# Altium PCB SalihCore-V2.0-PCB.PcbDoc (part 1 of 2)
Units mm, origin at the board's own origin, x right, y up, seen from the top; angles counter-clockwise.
Board outline 97.26 x 87.25 mm, 4 copper layers (L1(sig), L2(GND), L3(PWR), L4(sig)), stack 1.589 mm thick; 79 components, 110 nets, 368 pads, 235 vias.
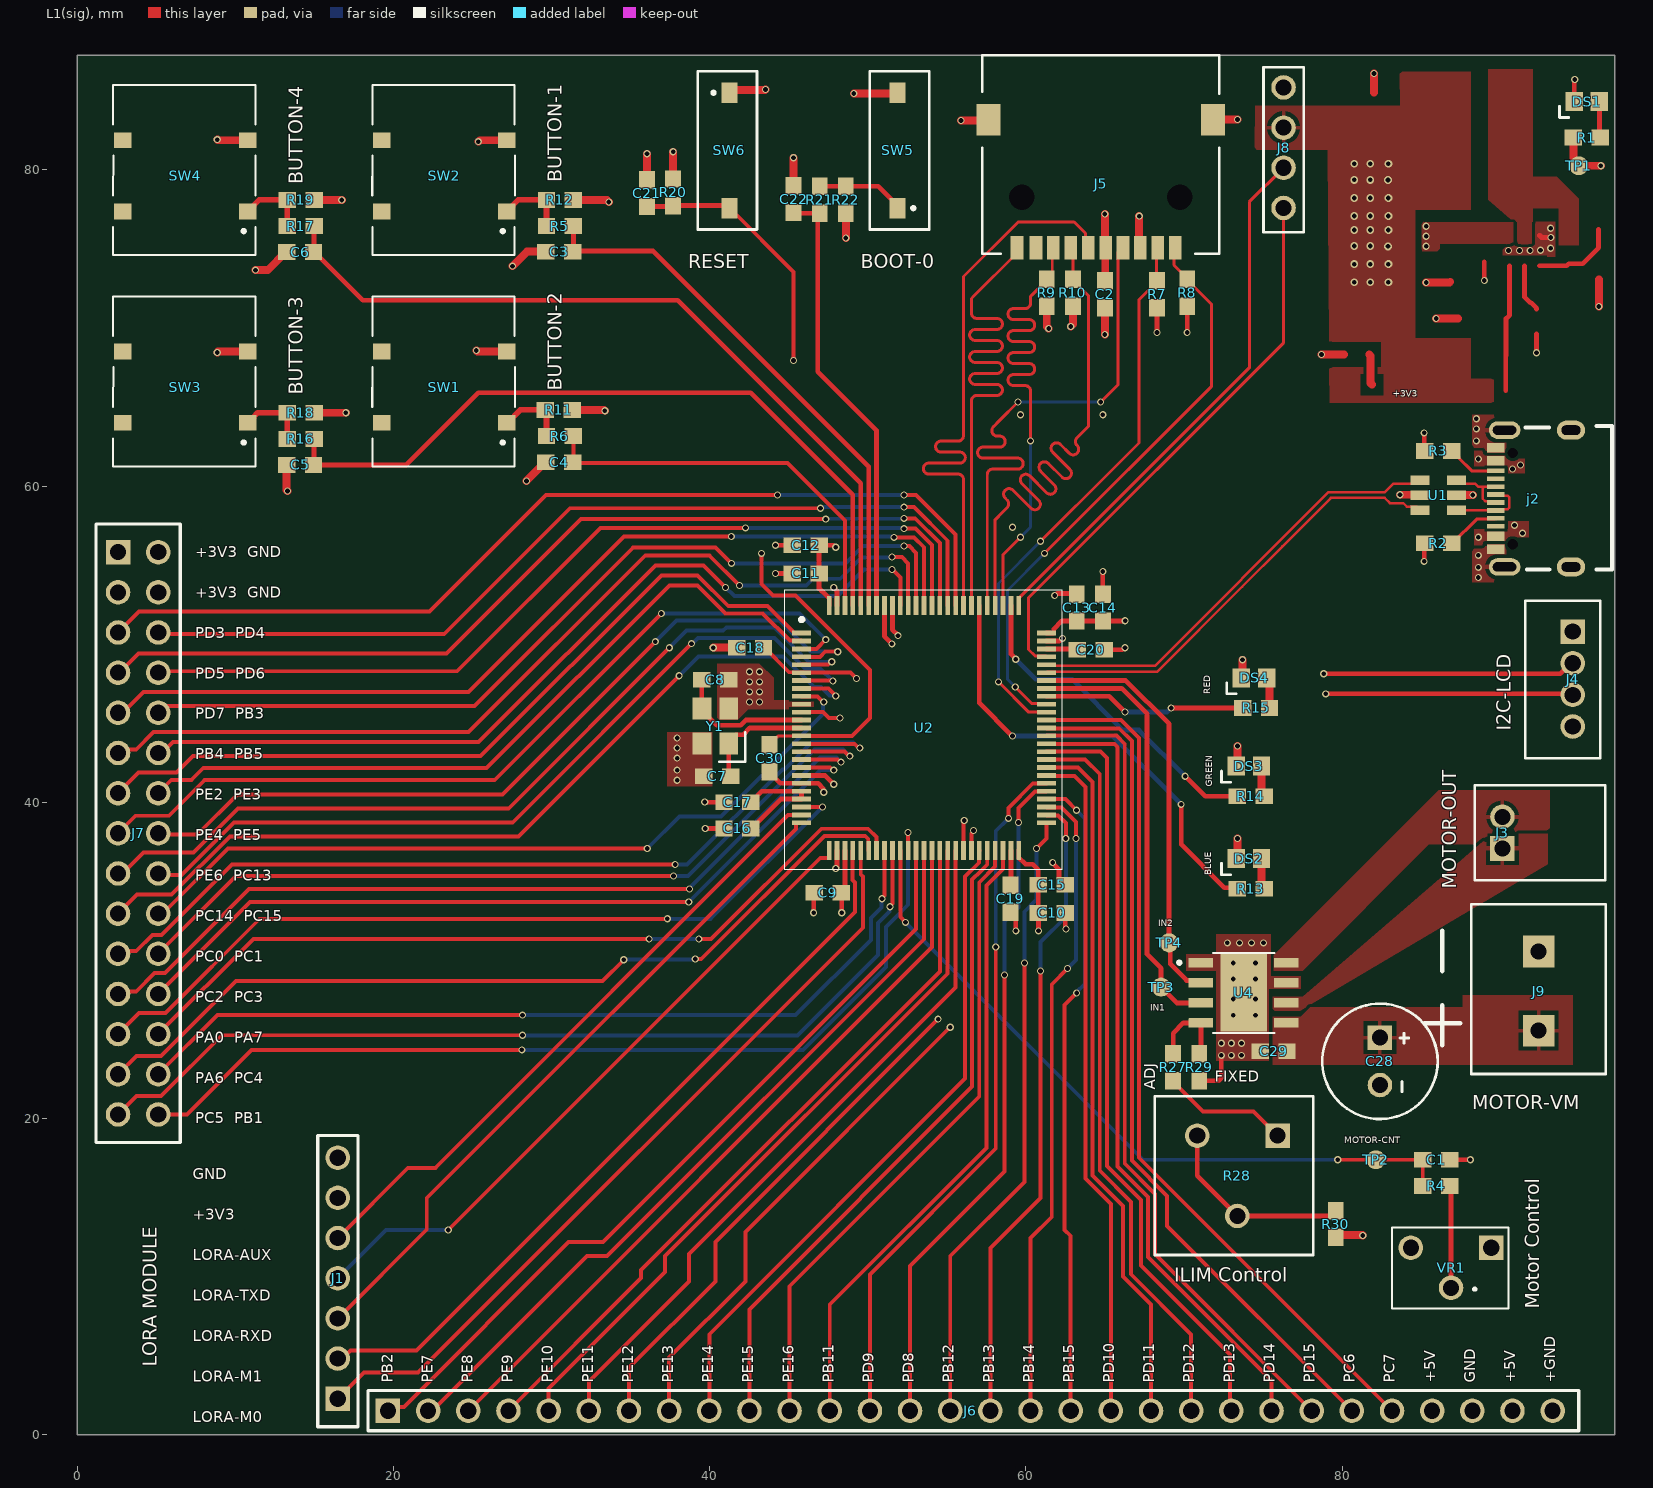
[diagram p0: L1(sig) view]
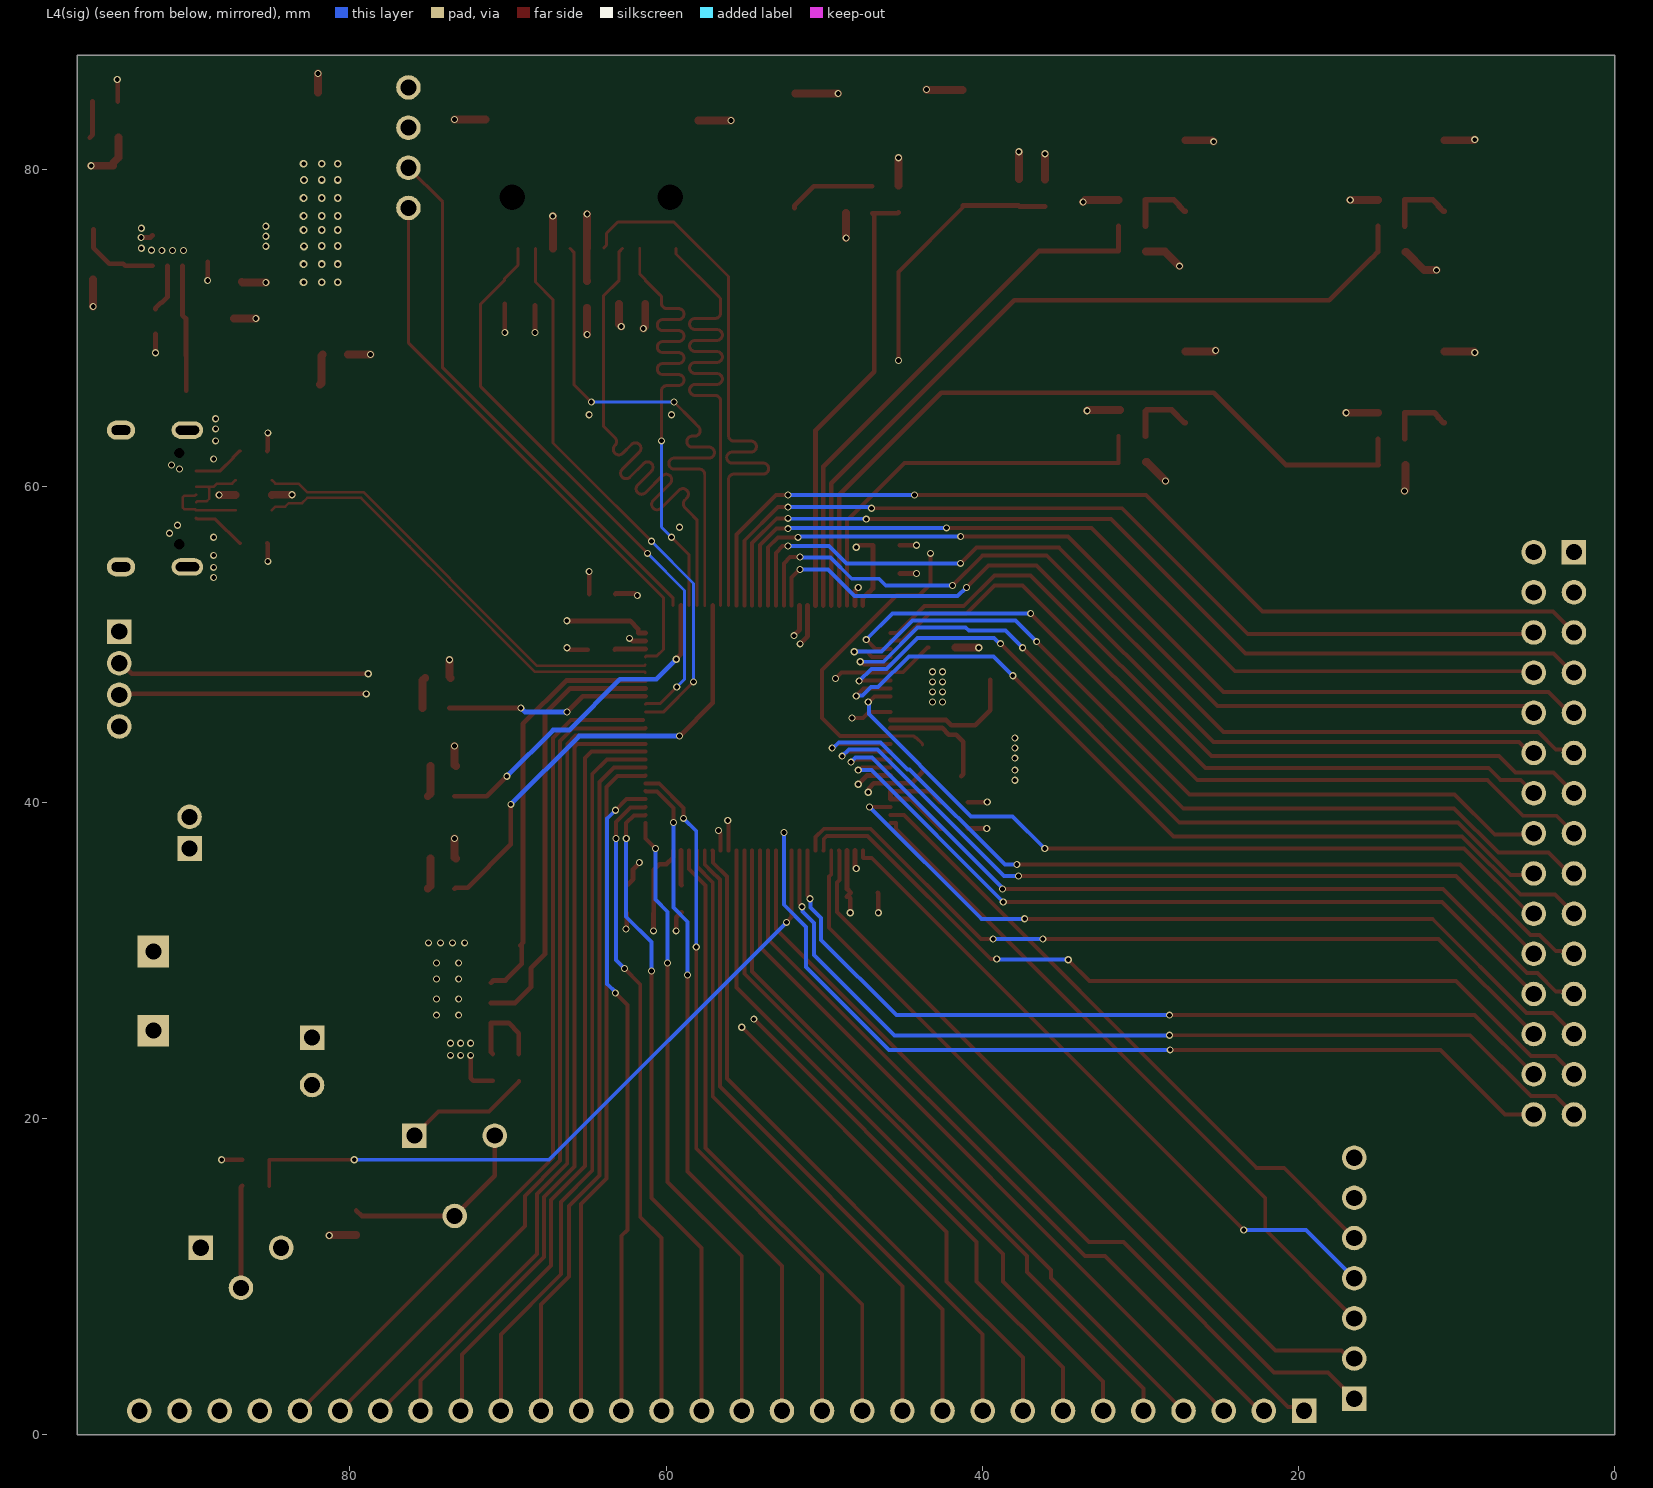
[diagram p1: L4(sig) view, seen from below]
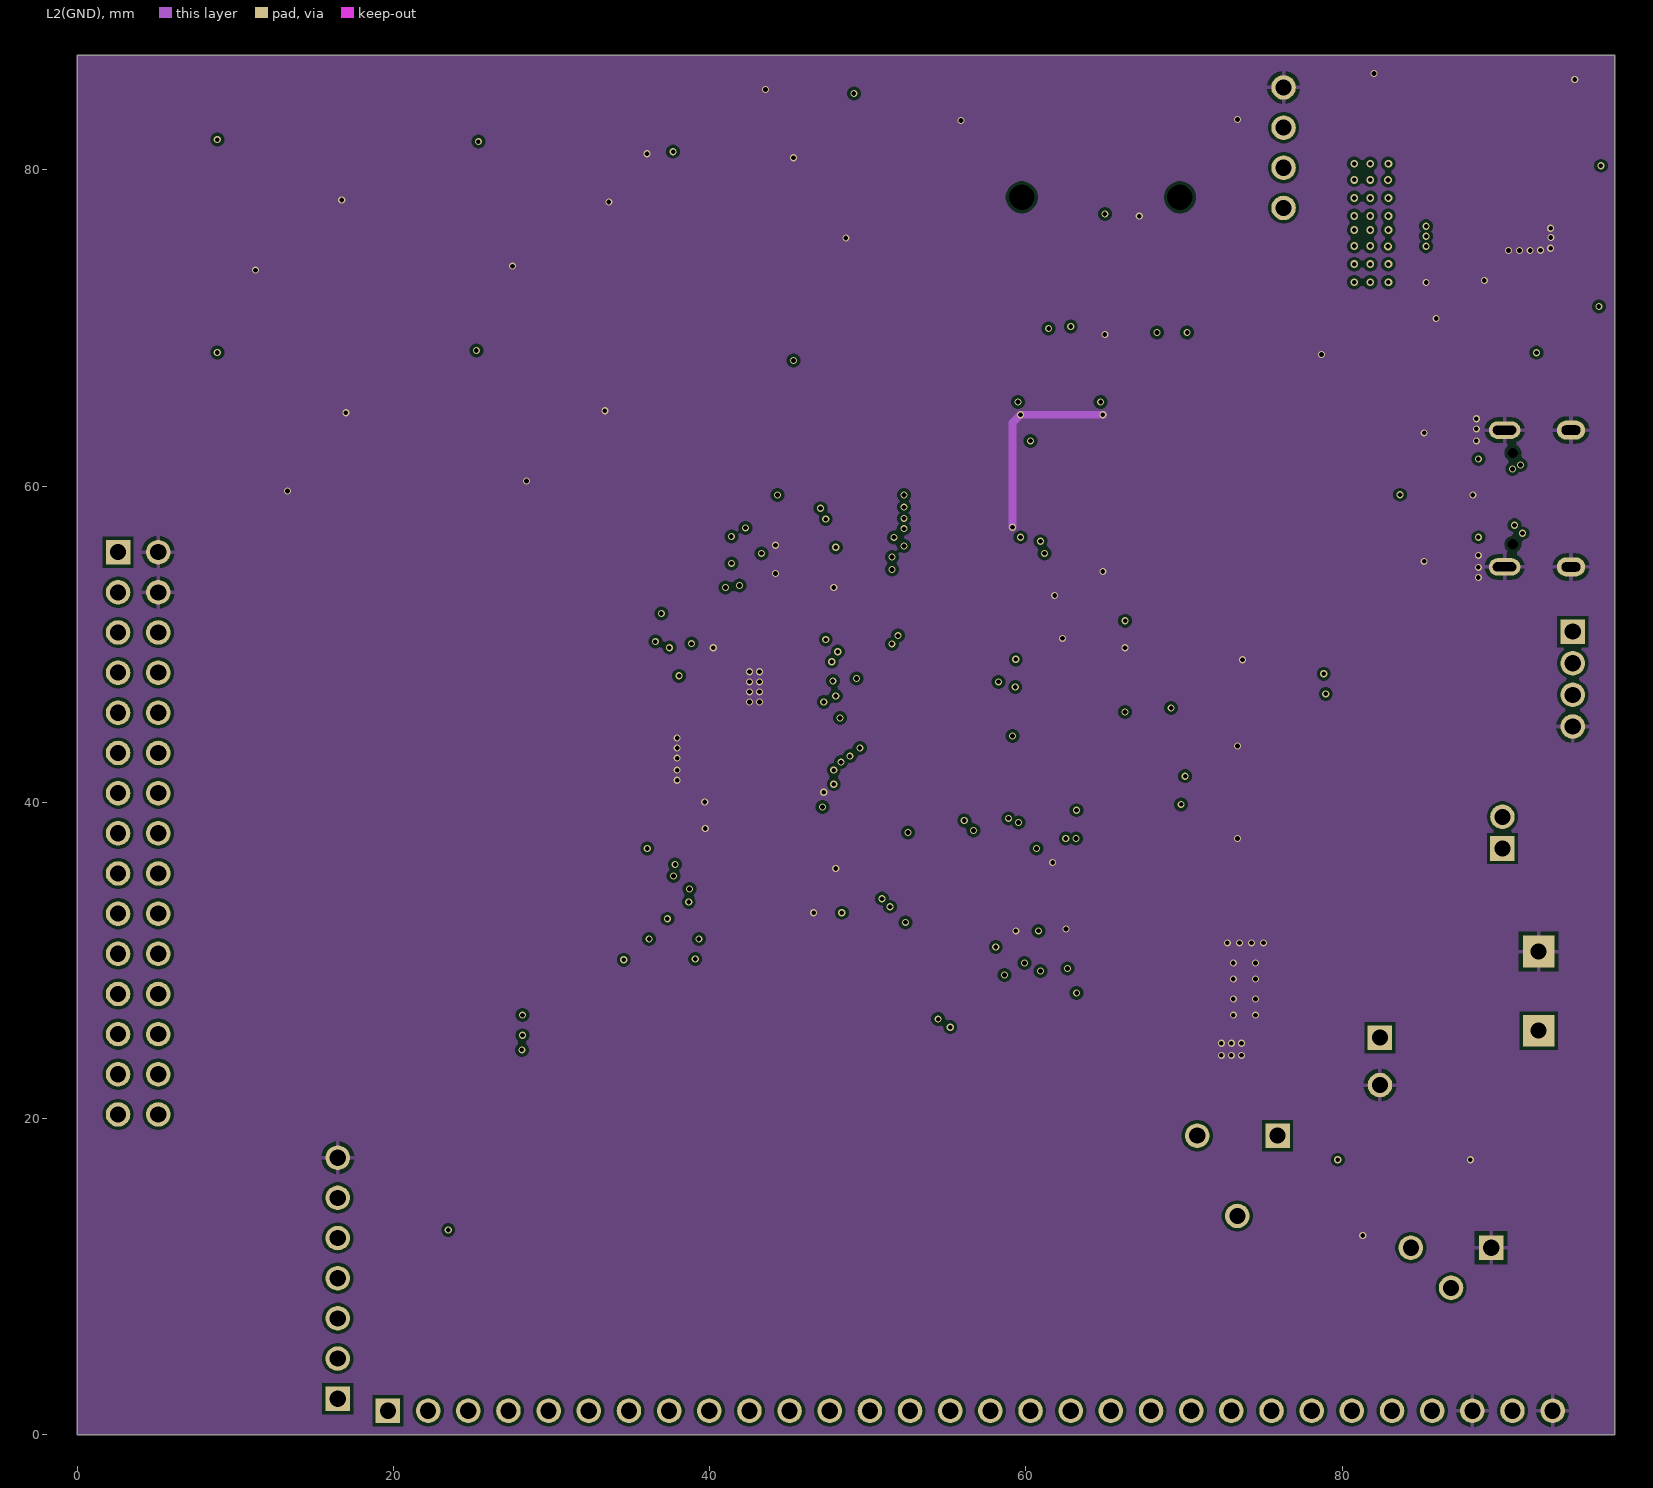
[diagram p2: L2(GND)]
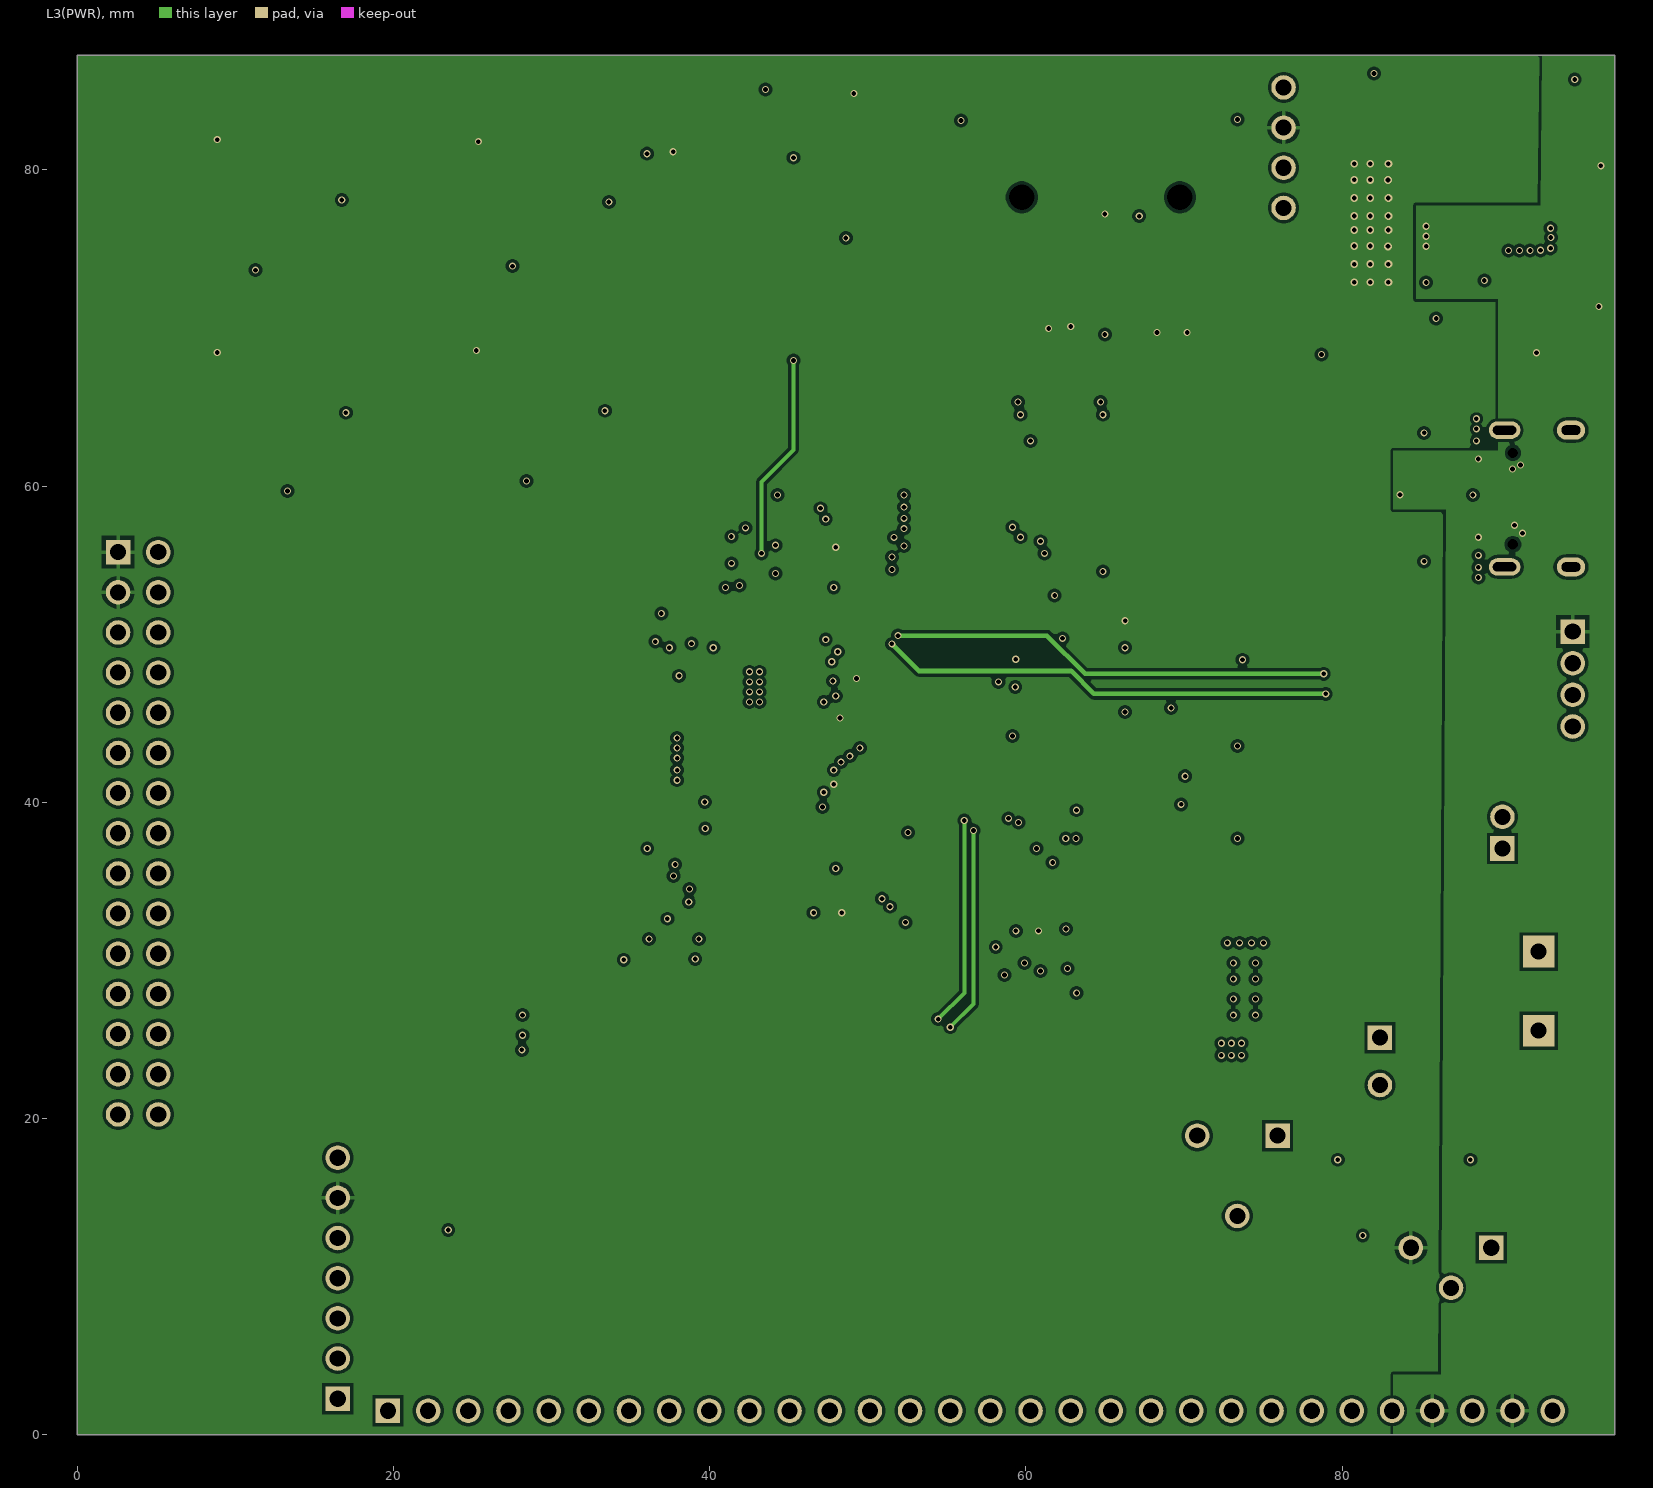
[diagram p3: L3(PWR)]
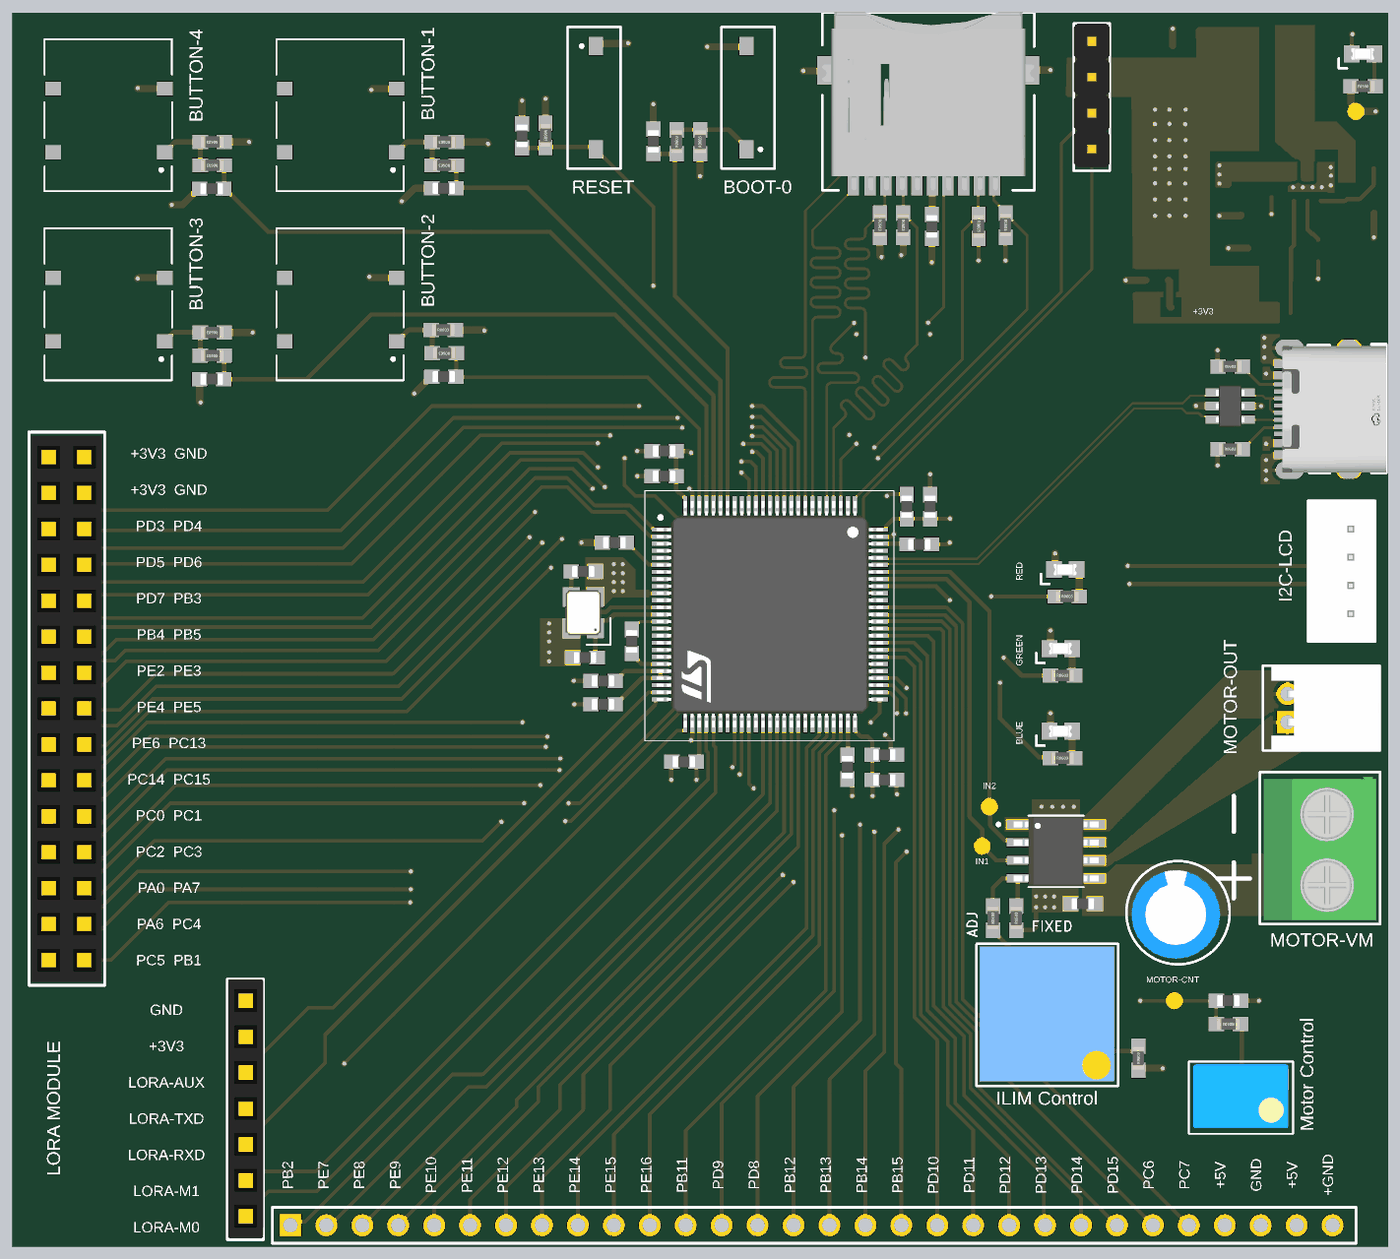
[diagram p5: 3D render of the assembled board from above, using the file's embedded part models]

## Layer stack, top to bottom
Top Solder: solder mask 0.0102, Solder Resist, Dk 3.5
L1(sig): signal copper 0.035
Dielectric 2: prepreg 0.1118, PP-015, Dk 4.3
L2(GND): signal copper 0.0152
Dielectric 1: dielectric 1.265, FR-4, Dk 4.8
L3(PWR): signal copper 0.0152
Dielectric 3: prepreg 0.1118, PP-015, Dk 4.3
L4(sig): signal copper 0.035
Bottom Solder: solder mask 0.0102, Solder Resist, Dk 3.5

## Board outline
0,0 97.259,0 97.259,87.249 0,87.249

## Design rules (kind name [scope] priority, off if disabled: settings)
Clearance [All] p1: gap=0.2 ignorepadtopadclearanceinfootprint=TRUE except(0.45: THPad-THPad)
DiffPairsRouting DIF90 [InDifferentialPairClass('DIFF90')] p1: maxlimit=0.254 minlimit=0.127 mostfreqgap=0.254 toplayer_mingap=0.203 toplayer_maxgap=0.203 toplayer_prefgap=0.203 toplayer_minwidth=0.158 toplayer_maxwidth=0.158 toplayer_prefwidth=0.158 bottomlayer_mingap=0.203 bottomlayer_maxgap=0.203 bottomlayer_prefgap=0.203 bottomlayer_minwidth=0.158 bottomlayer_maxwidth=0.158 bottomlayer_prefwidth=0.158 impedanceprofiledriven=TRUE impedanceprofileid={5F955A82-2F0E-4BEB-80A9-1F7B67A32B08} impedanceprofilevalue=90.000000 maxuncoupledlength=12.7
HoleToHoleClearance HoleToHoleClearance(pad) [All] p1: gap=0.254 allowstackedmicrovias=FALSE
Length [InNetClass('SE50')] p1: maxlimit=40 minlimit=37.42
MatchedLengths DIFF-PAIR [InDifferentialPairClass('DIFF90')] p1: tolerance=3.81 checknetsindiffpair=TRUE checkdiffpairvsdiffpair=FALSE checkxsignals=FALSE checkothers=FALSE
MinimumAnnularRing pins [IsThruPin] p1: minimumring=0.254
MinimumSolderMaskSliver [All] p1: minsoldermaskwidth=0.1
PlaneConnect [All] p1: planeconnectstyle=Direct reliefexpansion=0.508 reliefentries=4 reliefconductorwidth=0.254 reliefairgap=0.254
PolygonConnect ViasConnectRule [IsVia vs IsVia] p1: connectstyle=Direct reliefconductorwidth=0.254 reliefentries=4 polygonreliefangle="90 Angle" airgapwidth=0.254
PolygonConnect [All] p2: thpad.connectstyle=Relief thpad.reliefconductorwidth=0.254 thpad.reliefentries=4 thpad.polygonreliefangle="90 Angle" thpad.airgapwidth=0.254 smdpad.connectstyle=Direct smdpad.reliefconductorwidth=0.254 smdpad.reliefentries=4 smdpad.polygonreliefangle="90 Angle" smdpad.airgapwidth=0.254 via.connectstyle=Direct via.reliefconductorwidth=0.254 via.reliefentries=4 via.polygonreliefangle="90 Angle" via.airgapwidth=0.254
RoutingVias [All] p1: holewidth=0.25 width=0.35 viastyle="Through Hole" minholewidth=0.2 minwidth=0.3 maxholewidth=0.5 maxwidth=0.65
SilkToSolderMaskClearance [IsPad] p1: minsilkscreentomaskgap=0.2 clearancetoexposedcopper=FALSE
SolderMaskExpansion SolderMaskExpansion_Via [IsVia] p1: expansion=0.102 istentingtop=TRUE
SolderMaskExpansion [All] p2: expansion=0.045 istentingtop=FALSE
SupplyNets "Schematic Supply Nets_6" [InNet('+5V')] p1: voltage=0.000
SupplyNets "Schematic Supply Nets_5" [InNet('GND')] p2: voltage=0.000
SupplyNets "Schematic Supply Nets_4" [InNet('+3V3')] p3: voltage=0.000
SupplyNets "Schematic Supply Nets_2" [InNet('VM')] p4: voltage=0.000
UnRoutedNet [All] p1: checkbadconnections=TRUE
Width Width_45ohm [InNetClass('DIFF-45-SE')] p1: maxlimit=2.609 minlimit=0.193 preferedwidth=2.609 toplayer_maxwidth=0.193 toplayer_prefwidth=0.193 midlayer1_minwidth=2.609 midlayer2_minwidth=2.609 bottomlayer_maxwidth=0.193 bottomlayer_prefwidth=0.193 impedanceprofiledriven=TRUE impedanceprofileid={8CC7426C-BFE8-43E1-9E2F-CE8FD8D25B55} impedanceprofilevalue=45.000000 minimp=50.000000 maximp=50.000000 favimp=50.000000
Width Width_50ohm [InNetClass('SE50')] p2: maxlimit=2.17 minlimit=0.187 preferedwidth=2.17 toplayer_maxwidth=0.187 toplayer_prefwidth=0.187 midlayer1_minwidth=2.17 midlayer2_minwidth=2.17 bottomlayer_maxwidth=0.187 bottomlayer_prefwidth=0.187 impedanceprofiledriven=TRUE impedanceprofileid={F9704D24-9AF7-4F3A-B69D-D46F6DDFF038} impedanceprofilevalue=50.000000 minimp=50.000000 maximp=50.000000 favimp=50.000000
Width [All] p3: maxlimit=1 minlimit=0.2 preferedwidth=0.3
24 further rules are at their usual default settings.

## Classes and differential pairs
net class SE50: SDIO_CD SDIO_CK SDIO_CMD SDIO_D1 SDIO_D2 SDIO_D3 SDIO_DO
net class DIFF-45-SE: USB_N USB_OTG_FS_N USB_OTG_FS_P USB_P
differential pair class DIFF90: USB USB_OTG_FS
component class U_Motor-Driver: C28 C29 J9 R27 R28 R29 R30 U4 U7
component class U_Microcontroller: C7 C8 C9 C10 C11 C12 C13 C14 C15 C16 C17 C18 C19 C20 C21 C22 C30 J6 J7 J8 R20 R21 R22 SW5 SW6 TP2 TP3 TP4 U2 Y1
component class "U_LCD & SD-card & Lora": C1 C2 C3 C4 C5 C6 DS1 DS2 DS3 DS4 J1 J2 j2 J3 J4 J5 R1 R2 R3 R4 R5 R6 R7 R8 R9 R10 R11 R12 R13 R14 R15 R16 R17 R18 R19 SW1 SW2 SW3 SW4 TP1 U1 VR1
differential pair USB: +USB_P -USB_N
differential pair USB_OTG_FS: +USB_OTG_FS_P -USB_OTG_FS_N

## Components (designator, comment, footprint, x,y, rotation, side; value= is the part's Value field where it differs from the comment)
C1 "100nF" CAP-0603 85.956,17.399 r180 top
C2 "1uF" CAP-0603 65.001,72.136 r90 top
C3 "100nF" CAP-0603 30.499,74.831 r0 top
C4 "100nF" CAP-0603 30.499,61.516 r0 top
C5 "100nF" CAP-0603 14.098,61.341 r0 top
C6 "100nF" CAP-0603 14.098,74.803 r0 top
C7 "C?-0603" CAP-0603 40.49,41.656 r0 top
C8 "C?-0603" CAP-0603 40.363,47.752 r180 top
C9 "4.7uF" CAP-0603 47.475,34.29 r0 top
C10 "100nF" CAP-0603 61.645,33.009 r180 top
C11 "100nF" CAP-0603 46.078,54.483 r0 top
C12 "100nF" CAP-0603 46.078,56.261 r0 top
C13 "100nF" CAP-0603 63.223,52.324 r270 top
C14 "100nF" CAP-0603 64.874,52.324 r270 top
C15 "100nF" CAP-0603 61.645,34.787 r180 top
C16 "1uF" CAP-0603 41.76,38.354 r0 top
C17 "100nF" CAP-0603 41.76,40.005 r0 top
C18 "100nF" CAP-0603 42.561,49.784 r0 top
C19 "2.2uF" CAP-0603 59.032,33.909 r90 top
C20 "2.2uF" CAP-0603 64.112,49.657 r180 top
C21 "100nF" CAP-0603 36.037,78.536 r270 top
C22 "100nF" CAP-0603 45.316,78.155 r270 top
C28 "47uF" radial-D6.3-H12-P3 82.4,23.622 r270 top
C29 "100nF" CAP-0603 75.669,24.257 r0 top
C30 "100nF" CAP-0603 43.792,42.799 r90 top
DS1 "NCD0603R6" LED_0603 95.481,84.328 r180 top
DS2 "F.0603.00026/P2-0603B1TS2-06T-001" LED_0603 74.107,36.449 r180 top
DS3 "PSC-1608U50GC-G4" LED_0603 74.107,42.291 r180 top
DS4 "NCD0603R6" LED_0603 74.437,47.879 r180 top
J1 "PLG-F-7x1-2.54-THT" PLG-F-7x1-2.54-THT 16.487,9.906 r90 top
j2 "USB 3.1 TYPE C" "USB3.1-TYPEC-SHOU HAN" 89.732,56.018 r90 top
J3 "S2B-PH-K-S(LF)(SN)" S2B-PH-K-S(LF)(SN) 90.147,37.084 r90 top
J4 "JST-4x1-2.54-TH" JST-4x1-2.00-TH 94.592,50.8 r270 top
J5 "=comment" 112I-TA01 64.747,79.121 r180 top
J6 "PLG-F-30x1-2.54-THT" PLG-F-30x1-2.54-THT 19.662,1.524 r0 top
J7 "PLG-F-15x2-2.54-THT" PLG-F-15x2-2.54-THT 2.59,55.826 r270 top
J8 "PLG-M-4x1-2.54-THT" PLG-M-4x1-2.54-THT 76.304,81.407 r90 top
J9 "TB_2X1-5.08mm-F-THT" TB_2X1-5.08mm-F-THT 92.433,28.067 r270 top
R1 "1k" RES-0603 95.481,82.042 r180 top
R2 "5.1k" RES-0603 86.083,56.388 r0 top
R3 "5.1k" RES-0603 86.083,62.23 r0 top
R4 "1k" RES-0603 85.956,15.748 r180 top
R5 "1k" RES-0603 30.538,76.454 r180 top
R6 "1k" RES-0603 30.538,63.167 r180 top
R7 "47.5k" RES-0603 68.303,72.136 r270 top
R8 "47.5k" RES-0603 70.216,72.232 r270 top
R9 "47.5k" RES-0603 61.326,72.228 r270 top
R10 "47.5k" RES-0603 62.977,72.228 r270 top
R11 "1k" RES-0603 30.46,64.818 r0 top
R12 "1k" RES-0603 30.538,78.105 r180 top
R13 "1k" RES-0603 74.234,34.544 r0 top
R14 "1k" RES-0603 74.234,40.386 r0 top
R15 "1k" RES-0603 74.564,45.974 r0 top
R16 "1k" RES-0603 14.137,62.992 r180 top
R17 "1k" RES-0603 14.137,76.454 r180 top
R18 "1k" RES-0603 14.137,64.643 r180 top
R19 "1k" RES-0603 14.137,78.105 r180 top
R20 "10K" RES-0603 37.688,78.575 r270 top
R21 "10K" RES-0603 46.967,78.116 r90 top
R22 "10K" RES-0603 48.618,78.116 r90 top
R27 "R?-0603" RES-0603 69.319,23.241 r90 top
R28 "200k trimpot" POT_3386F 73.383,16.383 r180 top
R29 "R?-0603" RES-0603 70.97,23.241 r90 top
R30 "20k" RES-0603 79.606,13.335 r90 top
SW1 "tactile-spst" Tact-switch-12x12 23.218,66.258 r180 top
SW2 "tactile-spst" Tact-switch-12x12 23.218,79.629 r180 top
SW3 "tactile-spst" Tact-switch-12x12 6.835,66.258 r180 top
SW4 "tactile-spst" Tact-switch-12x12 6.835,79.629 r180 top
SW5 "SW+2-SMD" SW+2-SMD 51.888,81.232 r90 top
SW6 "SW+2-SMD" SW+2-SMD 41.252,81.232 r270 top
TP1 "Test-Point" "Test Point" 94.973,80.264 r270 top
TP2 "Test-Point" "Test Point" 82.146,17.399 r90 top
TP3 "Test-Point" "Test Point" 68.557,28.321 r90 top
TP4 "Test-Point" "Test Point" 69.065,31.115 r90 top
U1 "USBLC6-2SC6" SOT23-6 86.083,59.436 r180 top
U2 "STM32F407VGT6" LQFP-100-14x14 53.813,44.707 r270 top
U4 "DDRV8871DDAR" 8-PowerSOIC 73.779,27.955 r0 top
VR1 "10k" RES-TRIMPOT 86.845,10.668 r180 top
Y1 "8MHz" XTAL-TX32258M4LBDE2T-HM 40.363,44.831 r90 top

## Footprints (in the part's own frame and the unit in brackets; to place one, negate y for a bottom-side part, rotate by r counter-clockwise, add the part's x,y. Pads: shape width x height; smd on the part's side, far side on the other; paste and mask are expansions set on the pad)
8-PowerSOIC [mm]
  rrect5% 1.55x0.6 smd mask+0: 1(-2.7,1.905) 2(-2.7,0.635) 3(-2.7,-0.635) 4(-2.7,-1.905) 5(2.7,-1.905) 6(2.7,-0.635) 7(2.7,0.635) 8(2.7,1.905)
  rect 2.95x4.9 smd paste-3 mask+0: 9(0,0)
  silkscreen extent -4.17,-2.52 1.95,2.52, body extent -3,-2.45 3,2.45, height 1.7
112I-TA01 [mm]
  rect 0.8x1.5 smd: 1(3,4.05) 2(1.9,4.05) 3(0.8,4.05) 4(-0.3,4.05) 5(-1.4,4.05) 6(-2.5,4.05) 7(-3.6,4.05) 8(-4.7,4.05) 9(5.3,4.05) 10(4.1,4.05)
  rect 1.5x2 smd: 11(-7.1,-4.05) 11(7.1,-4.05)
  round 1 hole 1.6 unplated mask+0: ""(-5,0.85) ""(5,0.85)
  silkscreen extent -7.49,-8.14 7.49,4.43, body extent -7.5,-8.15 7.5,4.45, height 1.94
CAP-0603 [mm]
  rect 1.1x1 smd: 1(-0.85,0) 2(0.85,0)
  body extent -0.8,-0.4 0.8,0.4, height 0.9
JST-4x1-2.00-TH [mm]
  rect 1.55x1.55 hole 1.02: 1(0,0)
  round 1.55 hole 1.02: 2(2,0) 3(4,0) 4(6,0)
  silkscreen extent -1.94,-3 8,1.75, body extent -1.88,-2.96 7.98,1.71, height 5.89
LED_0603 [mm]
  rect 1.1x1.2 smd: A(-0.8,0) K(0.8,0)
  silkscreen extent 1.14,0.3 1.73,1.02, body extent -0.77,-0.4 0.83,0.4, height 0.55
LQFP-100-14x14 [mm]
  rect 0.3x1.2 smd mask+0.05: 1(-6,-8) 2(-5.5,-8) 3(-5,-8) 4(-4.5,-8) 5(-4,-8) 6(-3.5,-8) 7(-3,-8) 8(-2.5,-8) 9(-2,-8) 10(-1.5,-8) 11(-1,-8) 12(-0.5,-8) 13(0,-8) 14(0.5,-8) 15(1,-8) 16(1.5,-8) 17(2,-8) 18(2.5,-8) 19(3,-8) 20(3.5,-8) 21(4,-8) 22(4.5,-8) 23(5,-8) 24(5.5,-8) 25(6,-8) 51(6,7.5) 52(5.5,7.5) 53(5,7.5) 54(4.5,7.5) 55(4,7.5) 56(3.5,7.5) 57(3,7.5) 58(2.5,7.5) 59(2,7.5) 60(1.5,7.5) 61(1,7.5) 62(0.5,7.5) 63(0,7.5) 64(-0.5,7.5) 65(-1,7.5) 66(-1.5,7.5) 67(-2,7.5) 68(-2.5,7.5) 69(-3,7.5) 70(-3.5,7.5) 71(-4,7.5) 72(-4.5,7.5) 73(-5,7.5) 74(-5.5,7.5) 75(-6,7.5)
  rect 1.2x0.3 smd mask+0.05: 26(7.75,-6.25) 27(7.75,-5.75) 28(7.75,-5.25) 29(7.75,-4.75) 30(7.75,-4.25) 31(7.75,-3.75) 32(7.75,-3.25) 33(7.75,-2.75) 34(7.75,-2.25) 35(7.75,-1.75) 36(7.75,-1.25) 37(7.75,-0.75) 38(7.75,-0.25) 39(7.75,0.25) 40(7.75,0.75) 41(7.75,1.25) 42(7.75,1.75) 43(7.75,2.25) 44(7.75,2.75) 45(7.75,3.25) 46(7.75,3.75) 47(7.75,4.25) 48(7.75,4.75) 49(7.75,5.25) 50(7.75,5.75) 76(-7.75,5.75) 77(-7.75,5.25) 78(-7.75,4.75) 79(-7.75,4.25) 80(-7.75,3.75) 81(-7.75,3.25) 82(-7.75,2.75) 83(-7.75,2.25) 84(-7.75,1.75) 85(-7.75,1.25) 86(-7.75,0.75) 87(-7.75,0.25) 88(-7.75,-0.25) 89(-7.75,-0.75) 90(-7.75,-1.25) 91(-7.75,-1.75) 92(-7.75,-2.25) 93(-7.75,-2.75) 94(-7.75,-3.25) 95(-7.75,-3.75) 96(-7.75,-4.25) 97(-7.75,-4.75) 98(-7.75,-5.25) 99(-7.75,-5.75) 100(-7.75,-6.25)
  silkscreen extent -8.75,-9.1 8.95,8.5, body extent -8,-8.25 8,7.75, height 1.6
PLG-F-7x1-2.54-THT [mm]
  rect 1.55x1.55 hole 1.02: 1(-7.62,0)
  round 1.55 hole 1.02: 2(-5.08,0) 3(-2.54,0) 4(0,0) 5(2.54,0) 6(5.08,0) 7(7.62,0)
  silkscreen extent -9.4,-1.27 9.02,1.27, body extent -9.27,-1.27 9.01,1.23, height 5
PLG-F-15x2-2.54-THT [mm]
  rect 1.55x1.55 hole 1.02: 1(0,0)
  round 1.55 hole 1.02: 2(0,2.54) 3(2.54,0) 4(2.54,2.54) 5(5.08,0) 6(5.08,2.54) 7(7.62,0) 8(7.62,2.54) 9(10.16,0) 10(10.16,2.54) 11(12.7,0) 12(12.7,2.54) 13(15.24,0) 14(15.24,2.54) 15(17.78,0) 16(17.78,2.54) 17(20.32,0) 18(20.32,2.54) 19(22.86,0) 20(22.86,2.54) 21(25.4,0) 22(25.4,2.54) 23(27.94,0) 24(27.94,2.54) 25(30.48,0) 26(30.48,2.54) 27(33.02,0) 28(33.02,2.54) 29(35.56,0) 30(35.56,2.54)
  silkscreen extent -1.78,-1.4 37.34,3.94, body extent -1.52,-1.25 37.08,3.75, height 8.5
PLG-F-30x1-2.54-THT [mm]
  rect 1.55x1.55 hole 1.02: 1(0,0)
  round 1.55 hole 1.02: 2(2.54,0) 3(5.08,0) 4(7.62,0) 5(10.16,0) 6(12.7,0) 7(15.24,0) 8(17.78,0) 9(20.32,0) 10(22.86,0) 11(25.4,0) 12(27.94,0) 13(30.48,0) 14(33.02,0) 15(35.56,0) 16(38.1,0) 17(40.64,0) 18(43.18,0) 19(45.72,0) 20(48.26,0) 21(50.8,0) 22(53.34,0) 23(55.88,0) 24(58.42,0) 25(60.96,0) 26(63.5,0) 27(66.04,0) 28(68.58,0) 29(71.12,0) 30(73.66,0)
  silkscreen extent -1.27,-1.27 75.31,1.27
PLG-M-4x1-2.54-THT [mm]
  round 1.55 hole 1.02: 1(-3.81,0) 2(-1.27,0) 3(1.27,0) 4(3.81,0)
  silkscreen extent -5.34,-1.27 5.08,1.27, body extent -5.08,-1.27 5.08,1.27, height 8.89
POT_3386F [mm]
  round 1.55 hole 1.02 paste-2539.97: 1(0,2.54) 3(2.54,-2.54)
  rect 1.55x1.55 hole 1.02 paste-2539.97: 2(-2.54,-2.54)
  silkscreen extent -4.8,-5.03 5.23,5, body extent -4.52,-4.84 5,4.69, height 4.9
radial-D6.3-H12-P3 [mm]
  rect 1.55x1.55 hole 1.02: 1(-1.5,0)
  round 1.55 hole 1.02: 2(1.5,0)
  silkscreen extent -3.65,-3.65 3.65,3.65, body extent -3.01,-3.3 3.27,2.98, height 11
RES-0603 [mm] "CASE: 0603"
  rect 1.1x1 smd: 1(-0.85,0) 2(0.85,0)
  body extent -0.8,-0.4 0.8,0.4, height 0.43
RES-TRIMPOT [mm]
  round 1.55 hole 1.02: 1(-0.05,1.374) 3(2.49,-1.166)
  rect 1.55x1.55 hole 1.02: 2(-2.59,-1.166)
  silkscreen extent -3.68,-2.44 3.68,2.67, body extent -3.35,-2.22 3.35,2.28, height 8.84
S2B-PH-K-S(LF)(SN) [mm]
  rect 1.55x1.55 hole 1.02: 1(0,0)
  round 1.55 hole 1.02: 2(2,0)
  silkscreen extent -2,-6.5 4,1.75, body extent -1.95,-6.45 3.95,1.15, height 4.83
SOT23-6 [mm]
  rect 1.2x0.6 smd: 1(-1.15,0.95) 2(-1.15,0) 3(-1.15,-0.95) 4(1.15,-0.95) 5(1.15,0) 6(1.15,0.95)
  body extent -1.4,-1.46 1.4,1.46, height 0.4
SW+2-SMD [mm]
  rect 1.3x1 smd: 1(-3.65,0) 2(3.65,0)
  silkscreen extent -5,-2 5,1.75
Tact-switch-12x12 [mm]
  rect 1.1x1 smd: 1(-3.95,2.25) 2(3.95,2.25) 3(-3.95,-2.25) 4(3.95,-2.25)
  silkscreen extent -4.46,-5.75 4.55,5
TB_2X1-5.08mm-F-THT [mm]
  rect 2x2 hole 1.02: 1(-2.5,0) 2(2.5,0)
  silkscreen extent -5.5,-4.25 5.25,4.25, body extent -5.15,-4 5,4, height 10
"Test Point" [mm]
  round 1.2 smd paste-0.6 mask+0.025: 1(0,0)
"USB3.1-TYPEC-SHOU HAN" [mm]
  rect 0.6x1.1 smd: 1(0,0) 2(0.8,0) 11(5.6,0) 12(6.4,0)
  rect 0.3x1.1 smd: 3(1.45,0) 4(1.95,0) 5(2.45,0) 6(2.95,0) 7(3.45,0) 8(3.95,0) 9(4.45,0) 10(4.95,0)
  oval 1.1x2 hole 0.58 slot 1.48 at 90 deg: 13(-1.125,-0.55) 14(7.525,-0.55)
  oval 1.2x1.8 hole 0.6 slot 1.2 at 90 deg: 13(-1.125,-4.75) 14(7.525,-4.75)
  round 0.3 hole 0.65 unplated mask+0: ""(0.305,-1.07) ""(6.085,-1.07)
  silkscreen extent -1.3,-7.35 7.77,-1.88, body extent -1.27,-7.38 7.67,0.2, height 2.86
XTAL-TX32258M4LBDE2T-HM [mm]
  rect 1.4x1.2 smd: 1(-1.1,-0.85) 2(1.1,-0.85) 3(1.1,0.85) 4(-1.1,0.85)
  silkscreen extent -2.26,-1.91 -0.4,-0.25, body extent -1.6,-1.25 1.6,1.25, height 0.6

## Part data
C1 C3 C4 C5 C6 C10 C11 C12 C13 C14 C15 C17 C18 C21 C22 C29 C30: library part 2, "25V 100nF X7R ±10% 0603", distributor part number=C1590, manufacturer="Samsung Electro-Mechanics", package=0603, part number=CL10B104KA8NNNC
C2 C16: library part 3, "25V 1uF X7R ±10% 0603", distributor part number=C29936, manufacturer=samsung, package=0603, part number=CL10B105KA8NNNC
C7 C8: library part 2, distributor part number=C1590, manufacturer="Samsung Electro-Mechanics", package=0603, part number=CL10B104KA8NNNC
C9: library part 5, "35V 4.7uF X5R ±10% 0603 Multilayer Ceramic Capacitors MLCC - SMD/SMT ROHS", distributor part number=c162274, manufacturer=murata, package=0603, part number=GRM188R6YA475KE15D
C19 C20: library part 4, "16V 2.2uF X5R ±10% 0603 Multilayer Ceramic Capacitors MLCC - SMD/SMT", distributor part number=399-C0603C225K4PAC7867CT-ND, manufacturer=KEMET, package=0603, part number=C0603C225K4PAC7867
C28: library part 3, "47uF 63V, 6x12mm", distributor part number=DSTK2917, package=radial-tht
DS1 DS4: library part LED_Red-2V-25mA-0603, "25mA Colorless Transparent Lens 30mcd~80mcd 620nm~630nm -30℃~+85℃ Red 140° 65mW 1.6V~2.4V 0603 LED Indication - Discrete ROHS"
DS2: library part LED_Blue-2.9V-30mA-0603, "-40℃~+85℃ Blue 120° 0603 LED Indication - Discrete ROHS"
DS3: library part LED_Green-3V-10mA-0603, "Green 0603 LED Indication"
J1: library part 3, "7 rows, 1 column, female,2.54mm, tht pin header", package=THT
j2: library part USB3.1_TYPEC_SMD, "5A USB 3.1 1 Horizontal attachment 16P Female -25℃~+85℃ Type-C SMD USB Connectors ROHS", mfr.="SHOU HAN", mpn="TYPE-C 16PIN 2MD(073)"
J5: library part 112I-TA01
J6: library part 5, "30 rows, 1 column, female,2.54mm, tht pin header", package=THT
J7: library part 2, "15 rows, 2 column, female,2.54mm, tht pin header", package=THT
J8: library part 1, "4 rows, 1 column, 2.54mm, tht pin header", package=THT
R1 R4 R5 R6 R11 R12 R13 R14 R15 R16 R17 R18 R19: library part 16, "250mW Thick Film Resistors 75V ±100ppm/℃ ±5% 1.5kΩ 0603 Chip Resistor - Surface Mount ROHS", distributor part number=C966196, manufacturer=UNI-ROYAL, package=0603, part number=AS03W4J0152T5E
R2 R3: library part 32, "RES.(1608) 0603 5.1K Ohms 1% 1/10W-S 100PPM", distributor part number=0603SAF5101T5E, package=0603
R7 R8 R9 R10: library part 22, "47.5K-100mW-±1%-0603", package=0603
R20 R21 R22: library part 1, "250mW Thick Film Resistors 150V ±100ppm/℃ ±1% 10kΩ 0603 Chip Resistor - Surface Mount ROHS", distributor part number=C510087, manufacturer="ROHM Semicon", package=0603, part number=ESR03EZPF1002
R27 R29: library part 15, distributor part number=ERJ-3EKF2003V, package=0603
R28: library part RES-V-200K-250mW-THT
R30: library part 15, "20K-100mW-±1%-0603", distributor part number=ERJ-3EKF2003V, package=0603
U1: "17V Clamp 5A (8/20µs) Ipp Tvs Diode Surface Mount SOT-23-6"
U2: library part 1, "High-performance base series ARM Cortex-M4 MCU with DSP and FPU, featuring 1 MB Flash, 168 MHz CPU, ART accelerator, Ethernet, and FSMC", distributor part number=C12345, manufacturer=STMicroelectronics, package=LQFP-100(14x14)
U4: library part 1, "Unipolar Motor Driver NMOS PWM 8-SO PowerPad", distributor part number=296-43024-1-ND, manufacturer="Texas Instrument", package=8-PowerSOIC
VR1: library part RES-V-10K-250mW-THT
Y1: library part XTAL_8MHz-TX32258M4LBDE2T, mfr=Yajingxin, mpn=TX32258M4LBDE2T

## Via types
v1: diameter 0.45, hole 0.3, L1(sig) to L4(sig), tented both sides, 211 vias
v2: diameter 0.5, hole 0.3, L1(sig) to L4(sig), tented both sides, 24 vias

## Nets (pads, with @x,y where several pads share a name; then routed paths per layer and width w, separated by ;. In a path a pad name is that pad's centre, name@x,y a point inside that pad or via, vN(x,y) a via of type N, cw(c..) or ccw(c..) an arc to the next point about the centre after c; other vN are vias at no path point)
+3V3: C2.2 C9.2 C10.2 C11.2 C12.2 C13.2 C14.2 C15.2 C18.2 J1.6 J5.4 J7.1 J7.3 J8.3 R7.2 R8.2 R9.2 R10.2 R20.1 SW1.3 SW2.3 SW3.3 SW4.3 SW5.2 U2.6 U2.11 U2.19 U2.28 U2.50 U2.75 U2.100 VR1.3 | length 55.3
  L1(sig) w0.25: C18.2@43.411,49.784 43.461,49.784 45.013,48.232 45.788,48.232 U2.6@45.813,48.207 47.55,48.207 47.57,48.227 48.905,48.227 v1(49.3,47.833) ; U2.11@45.813,45.707 47.18,45.707 47.548,45.339 v1(48.253,45.339)
  L1(sig) w0.3: U2.19@45.813,41.707 47.297,41.707 v1(47.856,41.148) ; U2.100@47.563,52.457 47.563,52.907 47.149,53.321 47.14,53.321 46.928,53.533 C11.2@46.928,54.483 C12.2@46.928,56.261 47.816,56.261 47.943,56.134 v1(47.983,56.134) ; v1(48.364,33.02) 48.364,33.94 48.46,34.036 48.579,34.036 C9.2@48.325,34.29 48.563,34.528 U2.28@48.563,36.958 ; U2.50@59.563,36.957 59.563,36.507 59.988,36.083 60.438,36.083 60.795,35.725 C15.2@60.795,34.787 C10.2@60.795,33.009 60.81,32.994 v1(60.81,31.877) ; U2.75@61.313,50.707 61.763,50.707 61.763,50.964 62.273,51.474 C13.2@63.223,51.474 C14.2@64.874,51.474 66.275,51.474 v1(66.286,51.485) ; v1(68.303,69.723) R7.2@68.303,71.437 ; v1(70.208,69.723) 70.208,71.526 R8.2@70.216,71.534
  L1(sig) w0.5: v1(8.867,68.453) 8.922,68.508 SW3.3@10.785,68.508 ; v1(8.867,81.915) 8.903,81.879 SW4.3@10.785,81.879 ; v1(25.25,68.58) 25.322,68.508 SW1.3@27.168,68.508 ; v1(25.377,81.788) 25.468,81.879 SW2.3@27.168,81.879 ; R20.1@37.688,79.425 37.688,81.145 v1(37.696,81.153) ; v1(49.126,84.836) SW5.2@51.837,84.836 ; R9.2@61.326,71.529 61.326,70.096 v1(61.445,69.977) ; v1(62.842,70.104) 62.977,70.239 R10.2@62.977,71.529 ; C2.2@65.001,72.986 65.024,73.009 65.024,75.037 65.001,75.06 v1(65.001,77.216)
  other v2: 80.772,72.898 81.788,72.898 82.931,72.898 80.772,74.041 81.788,74.041 82.931,74.041 82.912,75.169 80.772,75.184 81.788,75.184 80.772,76.2 81.788,76.2 82.931,76.2 80.772,77.089 81.788,77.089 82.931,77.089 80.772,78.232 81.788,78.232 82.931,78.232 82.912,79.36 80.772,79.375 81.788,79.375 80.772,80.391 81.788,80.391 82.931,80.391
+5V: j2.2 j2.11 J4.1 J6.27 J6.29 R1.2 TP1.1 U1.5 | length 4.6
  L1(sig) w0.5: v1(83.67,59.457) 84.912,59.457 U1.5@84.933,59.436 ; R1.2@94.631,82.042 94.631,80.795 94.973,80.453 TP1.1@94.973,80.264 v1(96.37,80.264)
  other v1: 88.623,56.769 91.417,57.023 90.909,57.531 90.782,61.087 91.29,61.341 88.623,61.722 85.321,75.171 85.321,75.806 85.321,76.441
BLUE: DS2.A R13.2 | length 2
  L1(sig) w0.5: DS2.A@74.907,36.449 74.907,34.721 R13.2@75.084,34.544
BLUE_LED: R13.1 U2.81 | length 28.8
  L1(sig) w0.3: U2.81@57.063,52.457 57.063,46.292 v1(59.159,44.196) ; v1(69.827,39.878) 69.827,37.338 72.56,34.605 73.323,34.605 R13.1@73.384,34.544
  L4(sig) w0.3: v1(59.159,44.196) 65.509,44.196 v1(69.827,39.878)
BOOT0: C22.2 R21.1 U2.94 | length 28.1
  L1(sig) w0.3: C22.2@45.316,77.305 45.355,77.266 R21.1@46.967,77.266 46.84,77.139 46.84,67.24 50.563,63.517 U2.94@50.563,52.457
BTN1: R5.2 R12.2 SW2.1 | length 4.5
  L1(sig) w0.35: SW2.1@27.168,77.379 27.218,77.379 27.543,77.704 27.543,77.754 27.894,78.105 R12.2@29.688,78.105 R5.2@29.688,76.454
BTN2: R6.2 R11.1 SW1.1 | length 4.5
  L1(sig) w0.35: SW1.1@27.168,64.008 27.218,64.008 28.029,64.818 R11.1@29.61,64.818 29.688,64.74 R6.2@29.688,63.167
BTN3: R16.2 R18.2 SW3.1 | length 4.4
  L1(sig) w0.35: SW3.1@10.785,64.008 10.835,64.008 11.16,64.333 11.16,64.383 11.42,64.643 R18.2@13.287,64.643 R16.2@13.287,62.992
BTN4: R17.2 R19.2 SW4.1 | length 4.5
  L1(sig) w0.35: SW4.1@10.785,77.379 10.835,77.379 11.16,77.704 11.16,77.754 11.511,78.105 R19.2@13.287,78.105 R17.2@13.287,76.454
BTN_1: C3.2 R5.1 U2.95 | length 34.7
  L1(sig) w0.3: R5.1@31.388,76.454 31.388,74.87 36.435,74.87 50.063,61.242 U2.95@50.063,52.457
BTN_2: C4.2 R6.1 U2.98 | length 25.8
  L1(sig) w0.25: R6.1@31.388,63.167 31.388,61.477 31.398,61.468 44.935,61.468 48.563,57.84 U2.98@48.563,52.457
BTN_3: C5.2 R16.1 U2.97 | length 47.3
  L1(sig) w0.3: R16.1@14.987,62.992 14.987,61.38 C5.2@14.948,61.341 20.805,61.341 25.377,65.913 42.592,65.913 49.063,59.442 U2.97@49.063,52.457
BTN_4: C6.2 R17.1 U2.96 | length 50
  L1(sig) w0.3: R17.1@14.987,76.454 14.987,74.814 15.348,74.453 15.376,74.453 18.074,71.755 37.982,71.755 49.563,60.174 U2.96@49.563,52.457
CC1: j2.4 R2.2 | length 3.5
  L1(sig) w0.2: R2.2@86.933,56.388 86.983,56.388 88.514,57.918 89.682,57.918 j2.4@89.732,57.968
CC2: j2.10 R3.2 | length 3.4
  L1(sig) w0.2: R3.2@86.933,62.23 86.983,62.23 87.383,61.83 87.383,61.78 88.195,60.968 j2.10@89.732,60.968
GND: C1.1 C2.1 C3.1 C4.1 C5.1 C6.1 C7.1 C8.1 C9.1 C10.1 C11.1 C12.1 C13.1 C14.1 C15.1 C16.1 C17.1 C18.1 C19.1 C20.1 C21.1 C22.1 C28.2 C29.1 C30.1 DS1.K DS2.K DS3.K DS4.K J1.7 j2.1 j2.12 j2.13 j2.14 J4.4 J5.6 J5.11 J6.28 J6.30 J7.2 J7.4 J8.4 J9.1 R2.1 R3.1 R11.2 R12.1 R18.1 R19.1 R22.1 R29.1 R30.1 SW6.1 U1.2 U2.10 U2.20 U2.27 U2.74 U2.99 U4.1 U4.7 U4.9 VR1.2 Y1.2 Y1.4 | length 81.8
  L1(sig) w0.3: v1(39.699,40.017) 39.711,40.005 C17.1@40.91,40.005 ; v1(39.728,38.354) C16.1@40.91,38.354 ; C30.1@43.792,41.949 43.792,41.899 44.484,41.207 46.863,41.207 47.193,40.878 47.193,40.669 v1(47.221,40.64) ; v1(44.173,54.483) C11.1@45.228,54.483 ; v1(44.173,56.261) C12.1@45.228,56.261 ; v1(46.586,33.02) 46.586,34.251 C9.1@46.625,34.29 ; v1(47.856,53.594) 47.856,53.556 48.063,53.349 U2.99@48.063,52.457 ; v1(47.983,35.814) 48.063,35.894 U2.27@48.063,36.957 ; C19.1@59.032,33.059 59.371,32.72 v1(59.371,31.877) ; U2.74@61.313,50.207 62.107,50.207 62.277,50.376 v1(62.317,50.376) ; v1(61.699,36.195) 61.699,36.154 62.095,35.759 62.095,35.137 62.445,34.787 C15.1@62.495,34.787 ; v1(61.826,53.086) 61.867,53.086 61.994,53.213 63.184,53.213 C13.1@63.223,53.174 ; C10.1@62.495,33.009 62.495,32.04 v1(62.538,31.997) ; C14.1@64.874,53.174 v1(64.874,54.61) ; C20.1@64.962,49.657 66.104,49.657 66.231,49.784 v1(66.271,49.784) ; R29.1@70.97,22.391 72.192,22.391 72.367,22.567 v1(72.367,24.003) ; v1(85.194,55.245) 85.194,56.349 R2.1@85.233,56.388 ; v1(85.194,63.373) 85.194,62.269 R3.1@85.233,62.23 ; C1.1@86.806,17.399 v1(88.115,17.399) ; DS1.K@94.681,84.328 94.681,85.66 94.719,85.698 v1(94.719,85.725)
  L1(sig) w0.5: v1(11.28,73.66) 12.055,73.66 13.198,74.803 C6.1@13.248,74.803 ; C5.1@13.248,61.341 13.248,59.754 v1(13.312,59.69) ; R18.1@14.987,64.643 v1(16.995,64.643) ; R19.1@14.987,78.105 v1(16.741,78.105) ; v1(27.536,73.914) 28.453,74.831 C3.1@29.649,74.831 ; v1(28.425,60.325) 28.425,60.342 29.599,61.516 C4.1@29.649,61.516 ; R11.2@31.31,64.818 33.33,64.818 v1(33.378,64.77) ; R12.1@31.388,78.105 33.505,78.105 v1(33.632,77.978) ; C21.1@36.037,79.386 36.037,81.018 v1(36.045,81.026) ; v1(40.236,49.784) C18.1@41.711,49.784 ; SW6.1@41.252,85.057 43.505,85.057 v1(43.538,85.09) ; C22.1@45.316,79.005 v1(45.316,80.772) ; v1(48.618,75.692) R22.1@48.618,77.266 ; v1(55.91,83.132) J5.11@57.973,83.132 ; v1(65.001,69.596) C2.1@65.001,71.286 ; J5.6@67.173,75.032 v1(67.173,77.076) ; J5.11@71.426,83.185 v1(73.383,83.185) ; DS2.K@73.307,36.449 73.383,36.525 v1(73.383,37.719) ; DS3.K@73.307,42.291 73.383,42.367 v1(73.383,43.561) ; DS4.K@73.637,47.879 73.713,47.955 v1(73.713,49.022) ; R30.1@79.606,12.637 81.291,12.637 v1(81.313,12.615) ; U1.2@87.233,59.436 v1(88.273,59.436)
  L2(GND) w0.5: v1(59.159,57.404) 59.159,64.008 v1(59.667,64.516) v1(64.874,64.516)
  other v1: 73.002,24.003 73.637,24.003 72.367,24.765 73.002,24.765 73.637,24.765 73.129,26.543 74.526,26.543 73.129,27.559 74.526,27.559 73.129,28.829 74.526,28.829 73.129,29.845 74.526,29.845 72.748,31.115 73.51,31.115 74.272,31.115 75.034,31.115 37.95,41.402 37.95,42.037 37.95,42.799 37.95,43.434 37.95,44.069 42.522,46.355 43.157,46.355 42.522,46.99 43.157,46.99 42.522,47.625 43.157,47.625 42.522,48.26 43.157,48.26 88.623,54.229 88.623,54.864 88.623,55.626 88.496,62.865 88.496,63.627 88.496,64.262 90.536,74.904 91.223,74.899 91.899,74.904 92.56,74.917 93.195,75.044 93.195,76.314
GREEN: DS3.A R14.2 | length 2
  L1(sig) w0.5: DS3.A@74.907,42.291 74.907,40.563 R14.2@75.084,40.386
GREEN_LED: R14.1 U2.77 | length 21.1
  L1(sig) w0.3: U2.77@59.063,52.457 59.063,49.391 59.364,49.09 v1(59.364,49.049) ; v1(70.081,41.656) 71.351,40.386 R14.1@73.384,40.386
  L4(sig) w0.3: v1(59.364,49.049) 60.621,47.793 62.929,47.793 66.144,44.577 67.16,44.577 v1(70.081,41.656)
HSE_OSC_IN: C8.2 U2.12 Y1.3 | length 8.7
  L1(sig) w0.3: C8.2@39.513,47.752 39.513,45.831 40.463,44.881 41.958,44.881 42.284,45.207 U2.12@45.813,45.207
HSE_OSC_OUT: C7.2 U2.13 Y1.1 | length 7.1
  L1(sig) w0.3: Y1.1@41.213,43.731 41.213,41.783 C7.2@41.34,41.656 ; Y1.1@41.213,43.831 41.663,44.281 42.12,44.281 42.546,44.707 U2.13@45.813,44.707
ILIM: R27.2 R29.2 U4.4 | length 5.3
  L1(sig) w0.3: R27.2@69.319,24.091 69.319,25.4 69.969,26.05 U4.4@71.079,26.05 71.079,24.2 R29.2@70.97,24.091
LCD_I2C_SCL: J4.2 U2.92 | length 46
  L1(sig) w0.3: U2.92@51.563,52.457 51.563,50.914 51.92,50.557 v1(51.92,50.546) ; v1(78.844,48.133) 93.792,48.133 94.459,48.8 J4.2@94.592,48.8
  L3(PWR) w0.3: v1(51.92,50.546) 61.335,50.546 63.748,48.133 v1(78.844,48.133)
LCD_I2C_SDA: J4.3 U2.93 | length 47
  L1(sig) w0.3: U2.93@51.063,52.457 51.063,50.514 51.53,50.047 v1(51.53,50.026) ; v1(78.971,46.863) 94.529,46.863 J4.3@94.592,46.8
  L3(PWR) w0.3: v1(51.53,50.026) 53.243,48.313 62.86,48.313 64.31,46.863 v1(78.971,46.863)
LORA_AUX: J1.5 U2.24 | length 40.4
  L1(sig) w0.25: J1.5@16.487,12.446 20.932,16.891 22.657,16.891 44.973,39.207 U2.24@45.813,39.207
LORA_M0: J1.1 U2.30 | length 50.5
  L1(sig) w0.25: J1.1@16.487,2.286 18.138,3.937 21.569,3.937 49.703,32.072 49.703,35.312 49.563,35.452 U2.30@49.563,36.957
LORA_M1: J1.2 U2.29 | length 48.4
  L1(sig) w0.25: J1.2@16.487,4.826 16.776,4.826 17.284,5.334 21.456,5.334 49.2,33.078 49.2,34.925 49.038,35.087 49.038,36.359 49.038,36.932 U2.29@49.063,36.957
LORA_RXD: J1.3 U2.25 | length 43.7
  L1(sig) w0.25: J1.3@16.487,7.366 22.113,12.991 22.113,14.984 45.457,38.328 45.457,38.682 45.46,38.685 U2.25@45.813,38.685
LORA_TXD: J1.4 U2.26 | length 42.5
  L1(sig) w0.25: v1(23.475,12.956) 47,36.482 47.538,36.482 47.563,36.507 U2.26@47.563,36.957
  L4(sig) w0.25: J1.4@16.487,9.906 19.538,12.956 v1(23.475,12.956)
MOTOR_CNT: C1.2 R4.2 TP2.1 U2.35 | length 45.3
  L1(sig) w0.25: U2.35@52.063,36.957 52.063,32.75 v1(52.399,32.415) ; v1(79.733,17.399) TP2.1@82.146,17.399 C1.2@85.106,17.399 R4.2@85.106,15.748
  L4(sig) w0.25: v1(52.399,32.415) 67.414,17.399 v1(79.733,17.399)
MOTOR_IN1: TP3.1 U2.68 U4.3 | length 27.6
  L1(sig) w0.3: U2.68@61.313,47.207 66.054,47.207 67.668,45.593 67.668,30.406 68.557,29.517 TP3.1@68.557,28.321 69.558,27.32 U4.3@71.079,27.32
MOTOR_IN2: TP4.1 U2.69 U4.2 | length 26.6
  L1(sig) w0.3: U2.69@61.313,47.707 66.316,47.707 69.065,44.958 TP4.1@69.065,31.115 TP4.1@69.238,30.943 ; TP4.1@69.129,30.943 69.129,29.781 70.17,28.74 70.929,28.74 U4.2@71.079,28.59
MOTOR_OUT1: J3.1 U4.6
MOTOR_OUT2: J3.2 U4.8
NetDS1_A: DS1.A R1.1 | length 2.4
  L1(sig) w0.3: DS1.A@96.281,84.328 96.281,82.219 R1.1@96.458,82.042
NetR4_1: R4.1 VR1.1 | length 6.5
  L1(sig) w0.3: R4.1@86.806,15.748 86.895,15.659 VR1.1@86.895,9.294
NetR27_1: R27.1 R28.2 | length 8.1
  L1(sig) w0.25: R27.1@69.319,22.391 69.319,22.341 71.213,20.447 74.399,20.447 R28.2@75.923,18.923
